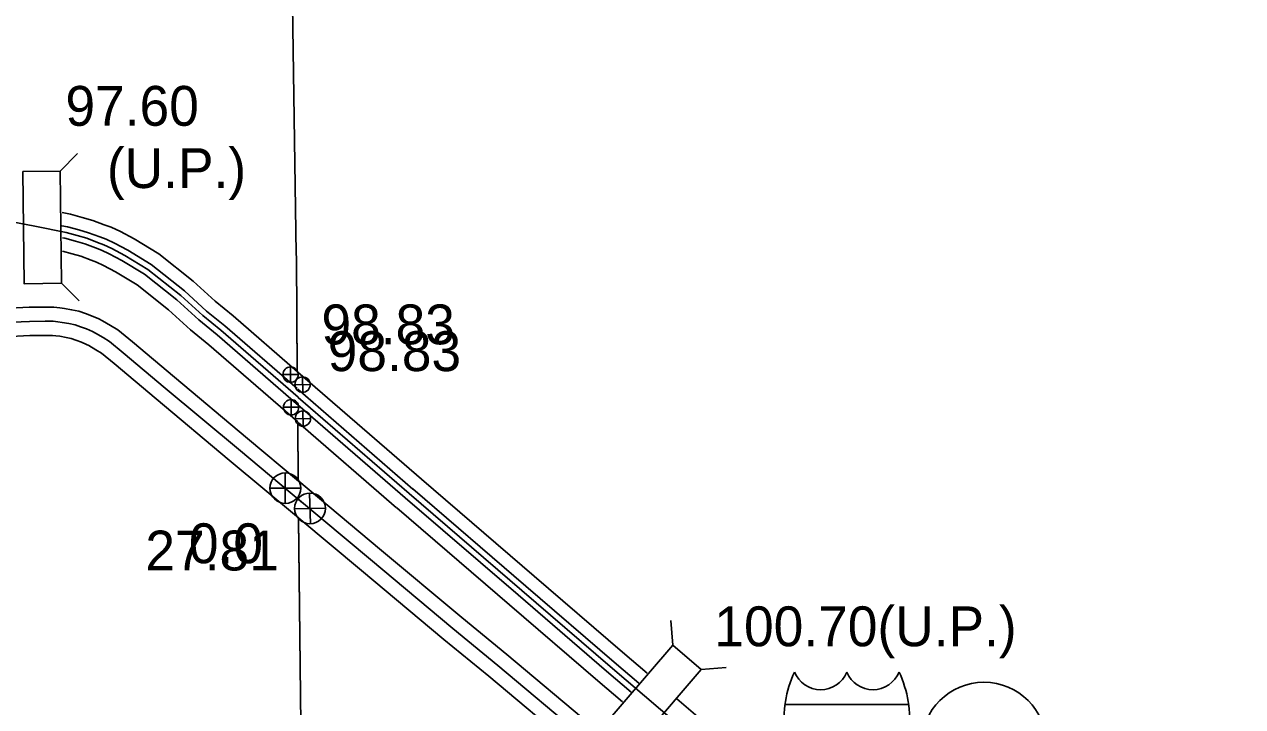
# Model space of a CAD drawing. Extents: x -83719 to 153526, y -11835 to 11446.
# Drawn here: x -664 to -233.7, y 857.9 to 1099 of the extents above; entities that cross this region are included whole.
import ezdxf

# ---------------------------------------------------------------- set-up
doc = ezdxf.new("R2010")
doc.units = 0
for name, color, linetype in [('Level 15', 7, 'Continuous'), ('Level 19', 7, 'Continuous'), ('Level 2', 7, 'Continuous'), ('Level 20', 7, 'Continuous'), ('Level 23', 7, 'Continuous'), ('Level 25', 7, 'Continuous'), ('Level 26', 7, 'Continuous'), ('Level 27', 7, 'Continuous'), ('Level 58', 7, 'Continuous'), ('Level 59', 7, 'Continuous')]:
    doc.layers.add(name, color=color, linetype=linetype)

msp = doc.modelspace()

# ---------------------------------------------------------------- linework, layer by layer
at = {"layer": 'Level 15'}
for points in [[(-671.31, 998.64), (-662.3, 999.08), (-656.66, 999.12), (-653.49, 999.14), (-651.48, 998.91), (-649.8, 998.66), (-647.3, 998.19), (-644.68, 997.69), (-642.4, 996.84), (-640.22, 996.09), (-637.71, 995.02), (-636.33, 994.3), (-633.55, 992.63), (-630.97, 991.05), (-625.81, 986.84), (-610.98, 974.33), (-585.16, 952.71), (-567.12, 937.64)], [(-670.82, 988.65), (-662.02, 989.08), (-656.6, 989.12), (-654.04, 989.14), (-652.79, 988.99), (-651.46, 988.8), (-649.16, 988.37), (-647.38, 988.03), (-645.79, 987.43), (-643.82, 986.75), (-641.99, 985.97), (-641.23, 985.58), (-638.73, 984.07), (-636.76, 982.88), (-632.2, 979.15), (-617.42, 966.68), (-591.58, 945.04), (-567.14, 924.63)], [(-567.05, 937.59), (-538.49, 913.73), (-509.41, 889.39)], [(-567.03, 924.54), (-544.91, 906.06), (-515.83, 881.72)], [(-509.45, 889.42), (-493.52, 876.34), (-463.58, 851.14)], [(-515.79, 881.69), (-499.92, 868.65), (-469.97, 843.44)]]:
    msp.add_lwpolyline(points, dxfattribs=at)
at = {"layer": 'Level 19'}
for points in [[(-650.6, 1032.54), (-647.68, 1031.96), (-643.5, 1030.84), (-639.81, 1029.77), (-635.74, 1028.24), (-633.28, 1027.33), (-630.04, 1025.79), (-625.19, 1023.22), (-616.51, 1017.92), (-604.37, 1008.35), (-596.6, 1001.19), (-590.27, 996.05), (-567.52, 976.3)], [(-650.67, 1027.88), (-648.72, 1027.49), (-644.73, 1026.43), (-641.26, 1025.42), (-637.35, 1023.95), (-635.06, 1023.1), (-632.1, 1021.69), (-627.45, 1019.23), (-619.13, 1014.15), (-607.35, 1004.85), (-599.6, 997.72), (-593.22, 992.54), (-567.61, 970.31)], [(-650.49, 1023.6), (-649.67, 1023.43), (-645.85, 1022.41), (-642.57, 1021.46), (-638.81, 1020.05), (-636.68, 1019.26), (-633.97, 1017.97), (-629.52, 1015.61), (-621.52, 1010.72), (-610.06, 1001.68), (-602.32, 994.57), (-595.9, 989.35), (-567.09, 964.34)], [(-650.5, 1018.91), (-647.08, 1018), (-644.02, 1017.11), (-640.41, 1015.75), (-638.47, 1015.03), (-636.02, 1013.87), (-631.79, 1011.63), (-624.14, 1006.96), (-613.03, 998.19), (-605.32, 991.1), (-598.85, 985.84), (-567.41, 958.55)], [(-567.37, 976.17), (-523.74, 938.3)], [(-567.36, 970.09), (-526.74, 934.84)], [(-567.35, 964.56), (-529.48, 931.69)], [(-567.22, 958.38), (-532.48, 928.23)], [(-523.76, 938.32), (-483.89, 904.02), (-452.73, 877.16), (-444.04, 869.71)], [(-526.75, 934.85), (-486.88, 900.54), (-455.72, 873.68), (-447, 866.21)], [(-529.47, 931.69), (-489.6, 897.39), (-458.43, 870.52), (-449.71, 863.04)], [(-532.46, 928.21), (-492.59, 893.91), (-461.42, 867.05), (-452.73, 859.6)], [(-433.52, 860.7), (-422.83, 851.54), (-402.93, 833.75), (-380.05, 812.25), (-347.82, 783.19), (-322.33, 759.07), (-308.79, 745.97), (-297.98, 735.95), (-295.63, 733.23), (-292.8, 730.72), (-290.53, 728.82), (-287.96, 726.76), (-285.47, 725.01), (-283.13, 723.49), (-273.34, 719.06), (-252.57, 710.37), (-233.73, 702.34)]]:
    msp.add_lwpolyline(points, dxfattribs=at)
at = {"layer": 'Level 2'}
for points in [[(-567.94, 1018.04), (-569.25, 1105.86), (-569.31, 1106.82), (-569.94, 1192.58), (-569.97, 1195.01), (-570.88, 1283.33), (-571.46, 1370.89), (-571.49, 1371.92), (-572.09, 1415.05)], [(-567.94, 1018.04), (-569.25, 1105.86), (-569.31, 1106.82), (-569.94, 1192.58), (-569.97, 1195.01), (-570.88, 1283.33), (-571.46, 1370.89), (-571.49, 1371.92), (-572.07, 1413.36)], [(-567.57, 976.17), (-567.9, 1016.54), (-567.94, 1018.04)], [(-567.57, 976.53), (-567.9, 1016.54), (-567.94, 1018.04)], [(-567.25, 937.59), (-567.42, 958.38)], [(-567.25, 938.1), (-567.42, 958.23)], [(-561.97, 574.36), (-563.34, 664.48), (-563.45, 665.01), (-565.03, 752.86), (-565.98, 840.04), (-566.19, 841.27), (-567.16, 924.54)], [(-561.97, 574.36), (-563.34, 664.48), (-563.45, 665.01), (-565.03, 752.86), (-565.98, 840.04), (-566.19, 841.27), (-567.16, 924.3)]]:
    msp.add_lwpolyline(points, dxfattribs=at)
at = {"layer": 'Level 20'}
for p, q in [((-651.3, 1047.14), (-645.15, 1053.44)), ((-650.84, 1007.55), (-644.55, 1001.4)), ((-434.97, 879.64), (-435.64, 888.41)), ((-434.97, 879.64), (-460.73, 849.57)), ((-424.94, 871.05), (-434.97, 879.64)), ((-450.71, 840.98), (-424.94, 871.05)), ((-424.94, 871.05), (-416.17, 871.72))]:
    msp.add_line(p, q, dxfattribs=at)
msp.add_lwpolyline([(-664.5, 1046.99), (-664.04, 1007.39), (-650.84, 1007.55), (-651.3, 1047.14)], close=True, dxfattribs=at)
at = {"layer": 'Level 23'}
msp.add_line((-395.36, 858.66), (-351.67, 858.66), dxfattribs=at)
for centre, radius, start, end in [((-354.76, 852.97), 41, 155.2204, 185.7928), ((-382.73, 873.92), 9.99, 202.1459, 337.3414), ((-364.3, 873.92), 9.99, 202.6586, 337.8541), ((-392.27, 852.97), 41, 354.2072, 24.7796)]:
    msp.add_arc(centre, radius, start, end, dxfattribs=at)
at = {"layer": 'Level 26'}
for p, q in [((-569.95, 972.55), (-569.95, 977.97)), ((-572.66, 975.26), (-567.25, 975.26)), ((-565.64, 969.03), (-565.76, 974.46)), ((-568.41, 971.68), (-562.99, 971.81)), ((-572.46, 963.73), (-567.05, 963.73)), ((-569.75, 961.02), (-569.75, 966.44)), ((-568.28, 959.67), (-562.86, 959.8)), ((-565.51, 957.02), (-565.63, 962.45)), ((-571.8, 929.74), (-571.8, 940.57)), ((-577.22, 935.15), (-566.38, 935.15)), ((-562.96, 922.57), (-563.21, 933.42)), ((-568.51, 927.87), (-557.66, 928.12))]:
    msp.add_line(p, q, dxfattribs=at)
for centre, radius in [((-569.95, 975.26), 2.71), ((-565.7, 971.74), 2.71), ((-569.75, 963.73), 2.71), ((-565.57, 959.74), 2.71), ((-571.8, 935.15), 5.42), ((-563.09, 927.99), 5.43)]:
    msp.add_circle(centre, radius, dxfattribs=at)
at = {"layer": 'Level 27'}
msp.add_circle((-325.07, 844.57), 22, dxfattribs=at)
at = {"layer": 'Level 59'}
for points in [[(-671.36, 1029.86), (-660.3, 1027.69), (-649.19, 1025.46), (-645.29, 1024.42), (-641.92, 1023.44), (-638.08, 1022), (-635.87, 1021.18), (-633.03, 1019.83), (-628.49, 1017.42), (-620.32, 1012.44), (-608.7, 1003.27), (-600.96, 996.14), (-594.56, 990.94), (-567.32, 967.3)], [(-671.06, 993.64), (-662.16, 994.08), (-656.63, 994.12), (-653.77, 994.14), (-652.13, 993.95), (-650.63, 993.73), (-648.23, 993.28), (-646.03, 992.86), (-644.09, 992.14), (-642.02, 991.42), (-639.85, 990.5), (-638.78, 989.94), (-636.14, 988.35), (-633.87, 986.97), (-629.01, 982.99), (-614.2, 970.51), (-588.37, 948.88), (-565.76, 930)], [(-567.24, 967.23), (-528.11, 933.27)], [(-567.55, 931.49), (-541.7, 909.9), (-512.62, 885.56)], [(-528.11, 933.27), (-488.24, 898.97), (-457.08, 872.1), (-427.23, 846.52)], [(-512.62, 885.56), (-496.72, 872.5), (-466.77, 847.29)]]:
    msp.add_lwpolyline(points, dxfattribs=at)

# ---------------------------------------------------------------- texts
at = {"layer": 'Level 25'}
for s, p in [('98.83', (-559.04, 985.97)), ('98.83', (-556.84, 976.51)), ('0.0', (-605.85, 908.62)), ('27.81', (-621.23, 906.06))]:
    msp.add_text(s, height=14.08, dxfattribs=at).set_placement(p)
at = {"layer": 'Level 58'}
for s, p in [('97.60', (-649.45, 1063.2)), ('(U.P.)', (-634.8, 1041.21)), ('100.70(U.P.)', (-420.29, 879.28))]:
    msp.add_text(s, height=14.08, dxfattribs=at).set_placement(p)

doc.saveas('drawing.dxf')
